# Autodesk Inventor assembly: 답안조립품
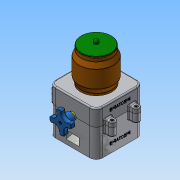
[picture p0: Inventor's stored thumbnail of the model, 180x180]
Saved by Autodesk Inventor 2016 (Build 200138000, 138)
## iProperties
Created: 2018-01
Part Number: 답안조립품
Material: 일반
Document SubType Name: Assembly
Designer: Administrator
Author: Administrator
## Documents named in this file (9)
- C:\Users\Administrator\Desktop\480107V1034\답안조립품.iam
- C:\Users\Administrator\Desktop\480107V1034\본체.ipt
- C:\Users\Administrator\Desktop\480107V1034\핸들축.ipt
- C:\Users\Administrator\Desktop\480107V1034\핸들.ipt
- C:\Users\Administrator\Desktop\480107V1034\볼트 M3x12.ipt
- C:\Users\Administrator\Desktop\480107V1034\본체커버.ipt
- C:\Users\Administrator\Desktop\480107V1034\용기.ipt
- C:\Users\Administrator\Desktop\480107V1034\용기캡.ipt
- C:\Users\Administrator\Desktop\480107V1034\볼트 M4x12.ipt
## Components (2 placed, 2 different names)
1. 핸들축:1
2. 핸들:1
